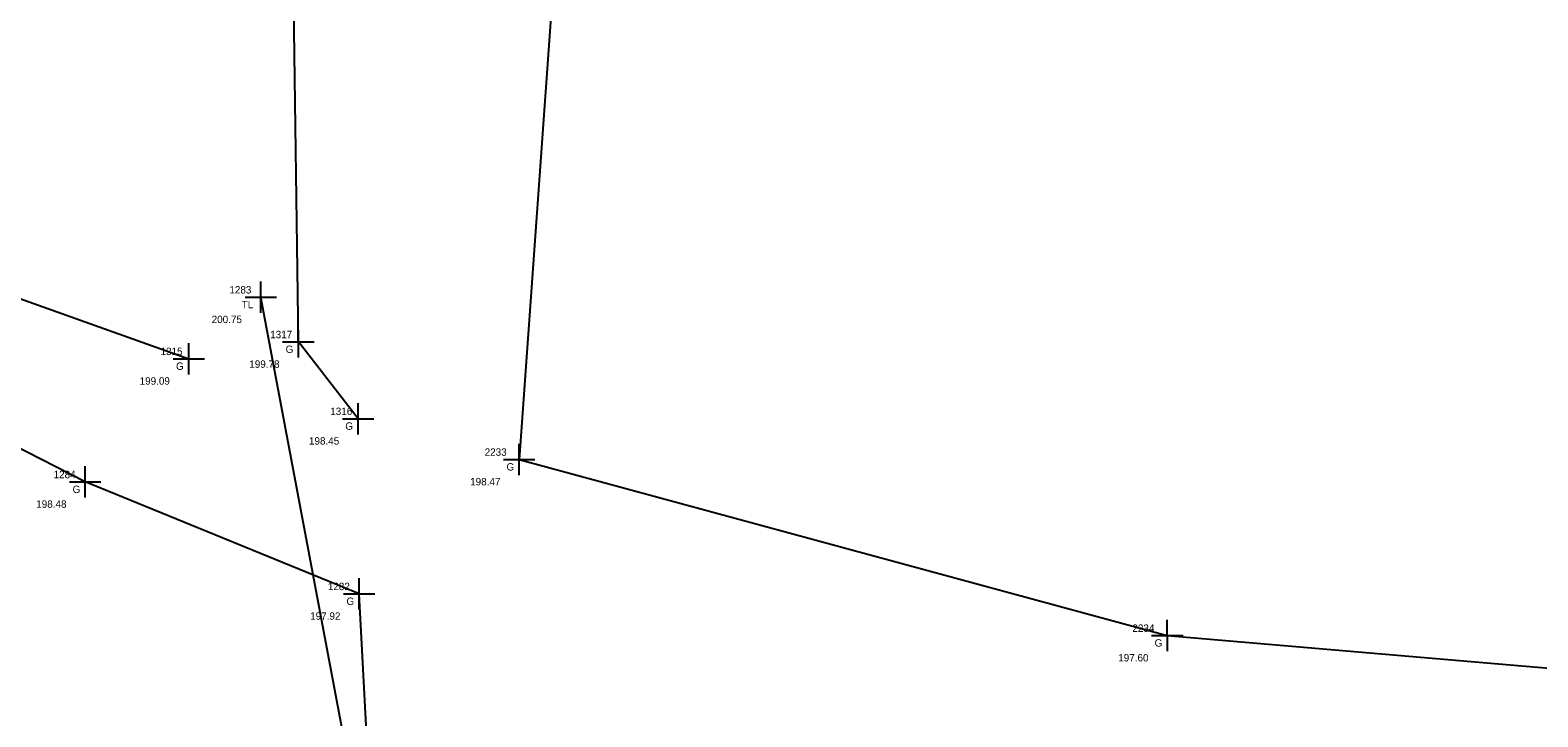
# Model space of a CAD drawing. Extents: x 1158983 to 1160032, y 610902 to 611573.
# Drawn here: x 1159660.7 to 1159721.8, y 611136.1 to 611163.9 of the extents above; entities that cross this region are included whole.
import ezdxf

# ---------------------------------------------------------------- set-up
doc = ezdxf.new("R2010")
doc.units = 0
for name, color, linetype in [('S_Field_Code', 7, 'Continuous'), ('S_Ground_Elevation', 7, 'Continuous'), ('S_Point_Elevation', 7, 'Continuous'), ('S_Point_Name', 7, 'Continuous'), ('S_Survey_Shot', 7, 'Continuous'), ('S_Trees_TreeLine', 7, 'Continuous')]:
    doc.layers.add(name, color=color, linetype=linetype)

msp = doc.modelspace()

# ---------------------------------------------------------------- linework, layer by layer
at = {"layer": 'S_Ground_Elevation'}
for points in [[(1159638.219, 611212.373), (1159636.237, 611197.229), (1159638.417, 611181.257), (1159645.223, 611166.982), (1159655.488, 611154.766), (1159667.117, 611150.624)], [(1159673.98, 611148.194), (1159671.561, 611151.308), (1159671.368, 611165.887), (1159673.116, 611179.063), (1159676.637, 611183.984), (1159682.051, 611189.85)], [(1159683.369, 611186.37), (1159680.513, 611146.541), (1159706.784, 611139.403), (1159766.662, 611134.29), (1159820.912, 611129.757), (1159888.671, 611122.169), (1159937.459, 611114.958), (1159962.2, 611115.558), (1159959.265, 611100.796), (1159986.294, 611096.455)], [(1159656.699, 610987.169), (1159659.81, 610998.002), (1159662.56, 611006.154), (1159673.42, 611011.162), (1159680.629, 611024.514), (1159686.412, 611068.065), (1159676.665, 611103.478), (1159674.701, 611128.373), (1159674.028, 611141.093), (1159662.925, 611145.632), (1159649.858, 611152.31)]]:
    msp.add_lwpolyline(points, dxfattribs=at)
at = {"layer": 'S_Survey_Shot'}
for p, q in [((1159670.038, 611152.484), (1159670.035, 611153.756)), ((1159669.4, 611153.119), (1159670.672, 611153.122)), ((1159670.036, 611153.12), (1159670.036, 611153.12)), ((1159671.563, 611150.672), (1159671.56, 611151.945)), ((1159667.118, 611149.988), (1159667.115, 611151.261)), ((1159670.925, 611151.307), (1159672.197, 611151.31)), ((1159671.561, 611151.308), (1159671.561, 611151.308)), ((1159666.48, 611150.623), (1159667.753, 611150.626)), ((1159667.117, 611150.624), (1159667.117, 611150.624)), ((1159673.982, 611147.558), (1159673.979, 611148.83)), ((1159673.344, 611148.193), (1159674.617, 611148.195)), ((1159673.98, 611148.194), (1159673.98, 611148.194)), ((1159680.515, 611145.905), (1159680.512, 611147.178)), ((1159662.926, 611144.995), (1159662.923, 611146.268)), ((1159679.877, 611146.54), (1159681.15, 611146.543)), ((1159680.513, 611146.541), (1159680.513, 611146.541)), ((1159662.288, 611145.63), (1159663.561, 611145.633)), ((1159662.925, 611145.632), (1159662.925, 611145.632)), ((1159674.029, 611140.457), (1159674.027, 611141.729)), ((1159673.392, 611141.092), (1159674.664, 611141.095)), ((1159674.028, 611141.093), (1159674.028, 611141.093)), ((1159706.786, 611138.767), (1159706.783, 611140.039)), ((1159706.148, 611139.401), (1159707.421, 611139.404)), ((1159706.784, 611139.403), (1159706.784, 611139.403))]:
    msp.add_line(p, q, dxfattribs=at)
at = {"layer": 'S_Trees_TreeLine'}
msp.add_lwpolyline([(1159686.412, 611068.065), (1159680.219, 611072.932), (1159676.665, 611103.478), (1159674.701, 611128.373), (1159670.036, 611153.12)], dxfattribs=at)

# ---------------------------------------------------------------- texts
at = {"layer": 'S_Field_Code'}
for s, p in [('TL', (1159669.264, 611152.67)), ('G', (1159671.046, 611150.858)), ('G', (1159666.602, 611150.174)), ('G', (1159673.465, 611147.744)), ('G', (1159679.999, 611146.091)), ('G', (1159662.41, 611145.182)), ('G', (1159673.513, 611140.643)), ('G', (1159706.27, 611138.953))]:
    msp.add_text(s, height=0.3, dxfattribs=at).set_placement(p)
at = {"layer": 'S_Point_Elevation'}
for s, p in [('200.75', (1159668.047, 611152.07)), ('199.78', (1159669.572, 611150.258)), ('199.09', (1159665.128, 611149.574)), ('198.45', (1159671.991, 611147.144)), ('198.47', (1159678.525, 611145.491)), ('198.48', (1159660.936, 611144.582)), ('197.92', (1159672.039, 611140.043)), ('197.60', (1159704.796, 611138.353))]:
    msp.add_text(s, height=0.3, dxfattribs=at).set_placement(p)
at = {"layer": 'S_Point_Name'}
for s, p in [('1283', (1159668.765, 611153.27)), ('1317', (1159670.418, 611151.458)), ('1315', (1159665.976, 611150.774)), ('1316', (1159672.854, 611148.344)), ('2233', (1159679.113, 611146.691)), ('1284', (1159661.64, 611145.782)), ('1282', (1159672.757, 611141.243)), ('2234', (1159705.37, 611139.553))]:
    msp.add_text(s, height=0.3, dxfattribs=at).set_placement(p)

doc.saveas('drawing.dxf')
